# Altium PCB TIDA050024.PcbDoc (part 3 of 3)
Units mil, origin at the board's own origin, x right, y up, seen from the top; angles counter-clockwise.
Board outline 5500.19 x 3301.39 mil, 4 copper layers (Top Layer, Signal Layer 1, Signal Layer 2, Bottom Layer), stack 46.8 mil thick; 153 components, 88 nets, 368 pads, 374 vias.
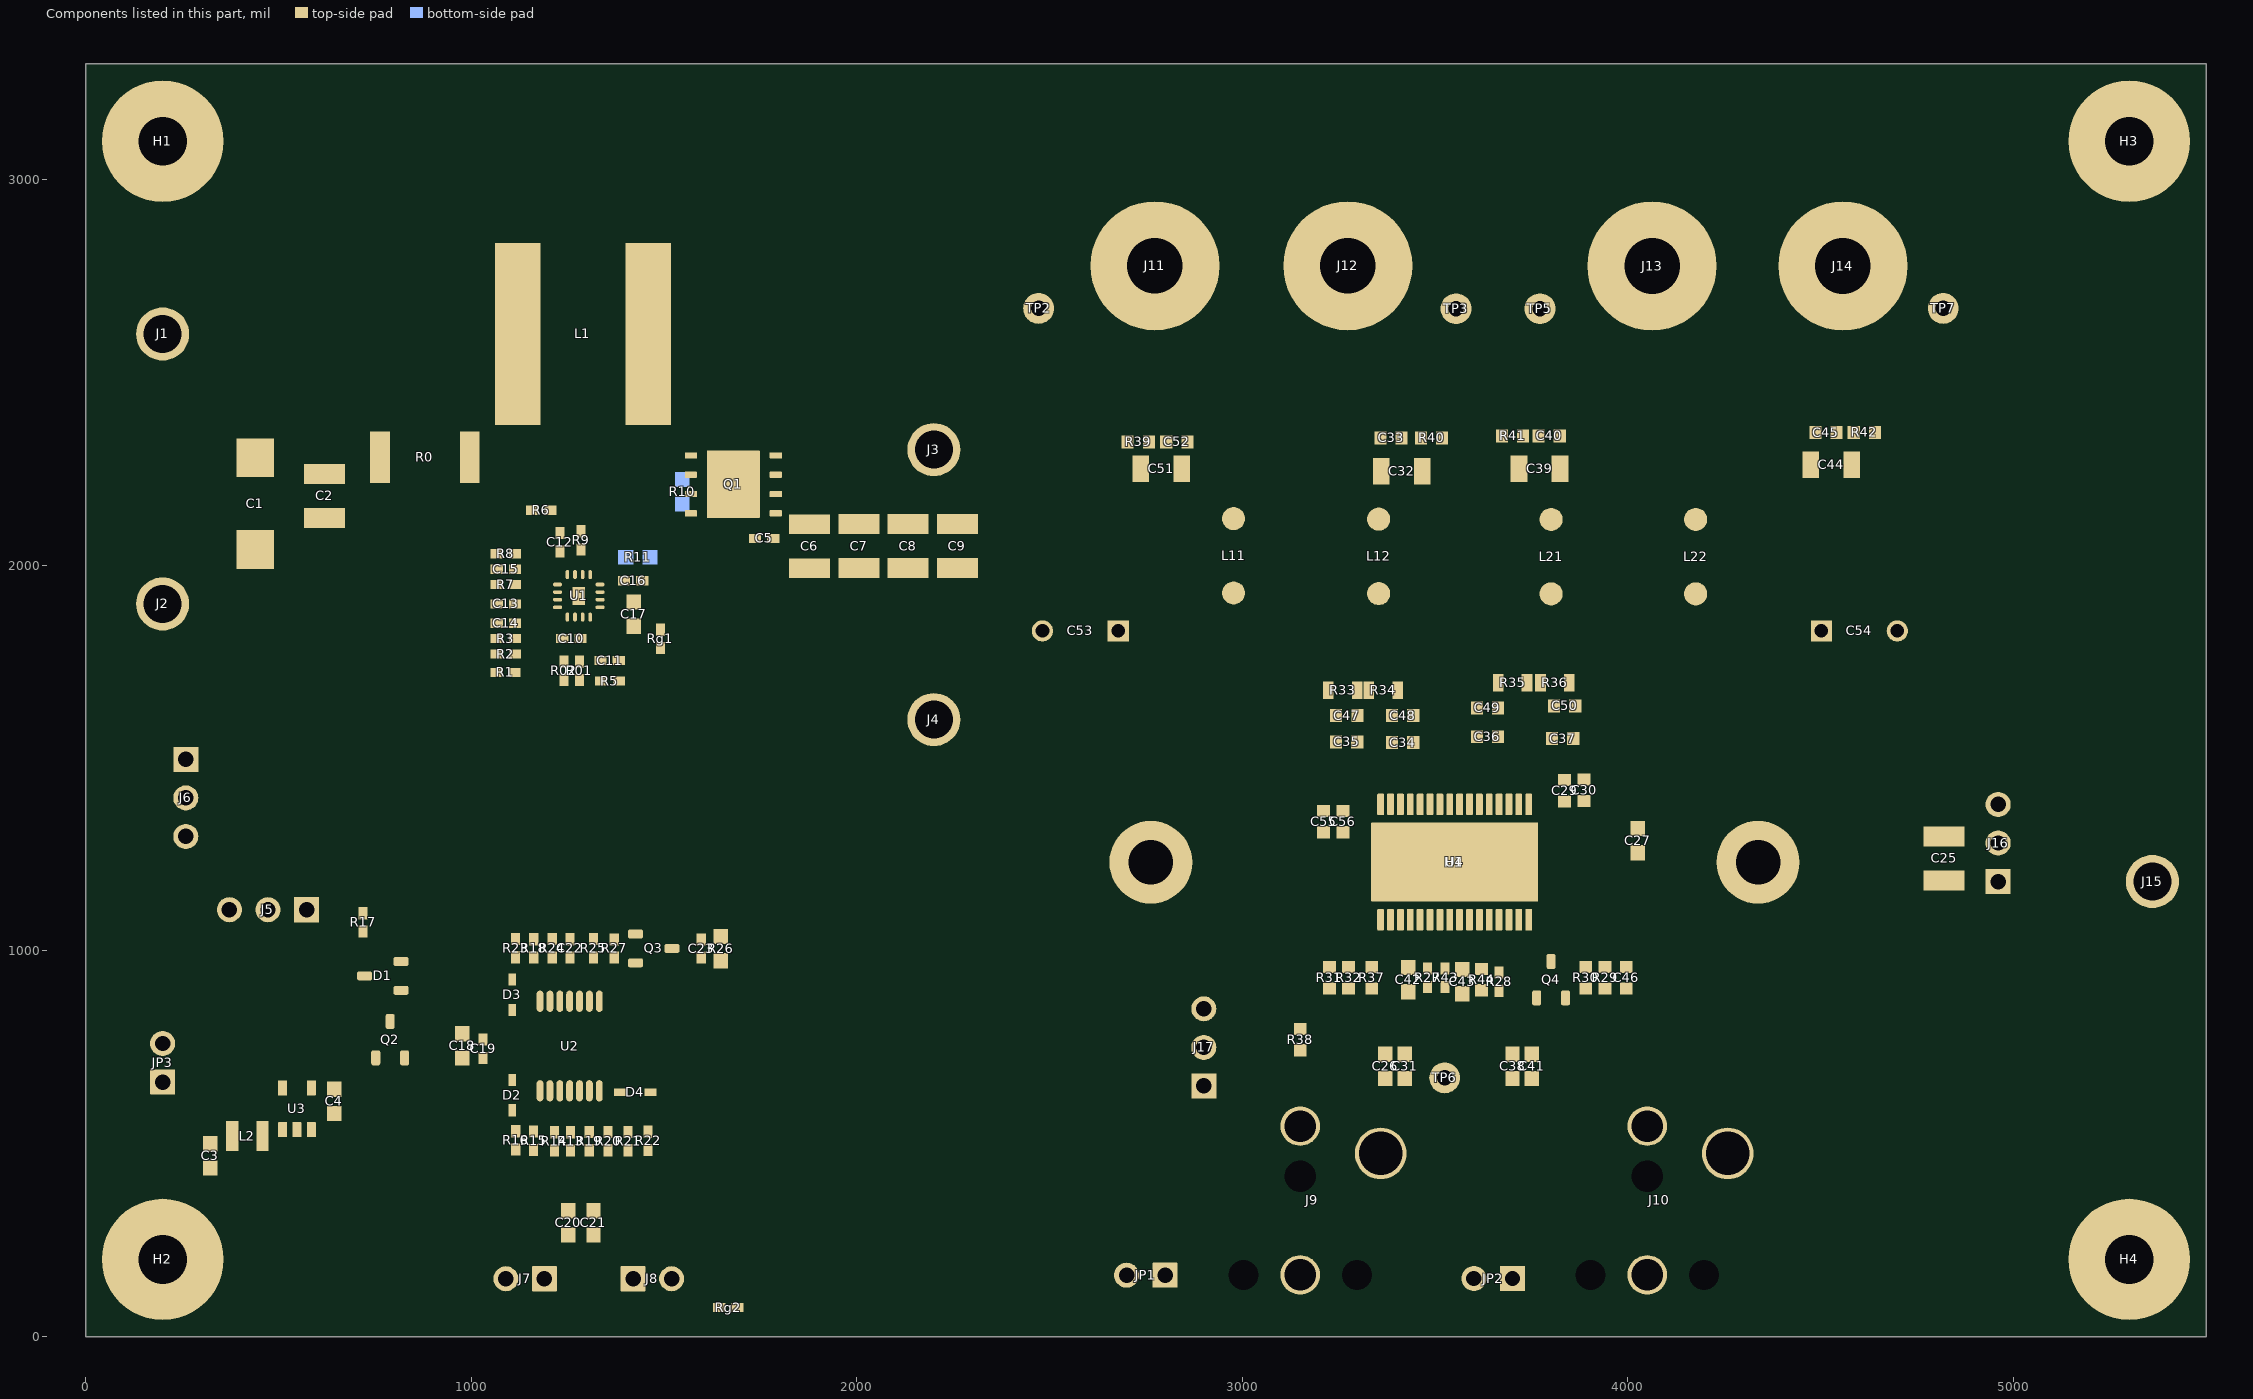
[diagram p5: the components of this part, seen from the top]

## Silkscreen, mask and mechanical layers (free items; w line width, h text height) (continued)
M11 Gerber Information:
  lines w10: -292,-930.17 6308,-930.17 ; -292,-726.83 6310,-726.83 ; -292,-523.5 -292,-1133.5 3713,-1133.5 6310,-1133.5 6310,-523.5 -291.5,-523.5 -291.5,-1133.5 1284,-1133.5 ; 2173,-1133.5 2173,-523.5 ; 3440,-726.83 3440,-523.5 ; 4280,-726.83 4280,-523.5 ; 4902,-1140 4902,-937.17
  text "ALL ARTWORK VIEWED FROM TOP SIDE" at -228.5,-655.67 h30
  text "BOARD #:" at 2248,-655.67 h30
  text ".PRJ_Number" at 2793.5,-655.67 h30
  text "REV:" at 3638,-655.67 h30
  text ".PCB_Rev" at 3929.5,-655.67 h30
  text "SVN REV:" at 4476,-655.67 h30
  text ".VersionControl_RevNumber" at 4982,-655.67 h30
  text "LAYER NAME =" at -228.5,-858.49 h30
  text "TID #:" at 2248,-859 h30
  text ".TID" at 2793.5,-859 h30
  text "PLOT NAME =" at -228.5,-1064.34 h30
  text ".plot_File_Name" at 577,-1064.34 h30
  text "GENERATED    :" at 2250,-1064.34 h30
  text ".Print_Date" at 3119.5,-1064.34 h30
  text ".Print_Time" at 3848.5,-1064.34 h30
  text "TEXAS INSTRUMENTS" at 5113,-1064.34 h30
M12 Stackup:
  drawing of 269 lines, arcs and shapes, not listed
  text "Layer" at 9767.84,7890 h30
  text "Name" at 9982.8,7890 h30
  text "Material" at 10462.67,7890 h30
  text "Thickness" at 10902.55,7890 h30
  text "Constant" at 11237.47,7890 h30
  text "Board Layer Stack" at 11532.4,7890 h30
  text "1" at 9767.84,7830 h30
  text "Top Overlay" at 9982.8,7830 h30
  text "2" at 9767.84,7770 h30
  text "Top Solder" at 9982.8,7770 h30
  text "Solder Resist" at 10462.67,7770 h30
  text "0.40mil" at 10902.55,7770 h30
  text "3.5" at 11237.47,7770 h30
  text "3" at 9767.84,7710 h30
  text "Top Layer" at 9982.8,7710 h30
  text "Copper" at 10462.67,7710 h30
  text "2.80mil" at 10902.55,7710 h30
  text "4" at 9767.84,7650 h30
  text "Dielectric1" at 9982.8,7650 h30
  text "FR-4" at 10462.67,7650 h30
  text "12.80mil" at 10902.55,7650 h30
  text "4.2" at 11237.47,7650 h30
  text "5" at 9767.84,7590 h30
  text "Signal Layer 1" at 9982.8,7590 h30
  text "Copper" at 10462.67,7590 h30
  text "1.40mil" at 10902.55,7590 h30
  text "6" at 9767.84,7530 h30
  text "Dielectric 3" at 9982.8,7530 h30
  text "12.80mil" at 10902.55,7530 h30
  text "4.2" at 11237.47,7530 h30
  text "7" at 9767.84,7470 h30
  text "Signal Layer 2" at 9982.8,7470 h30
  text "Copper" at 10462.67,7470 h30
  text "1.40mil" at 10902.55,7470 h30
  text "8" at 9767.84,7410 h30
  text "Dielectric 2" at 9982.8,7410 h30
  text "12.80mil" at 10902.55,7410 h30
  text "4.2" at 11237.47,7410 h30
  text "9" at 9767.84,7350 h30
  text "Bottom Layer" at 9982.8,7350 h30
  text "Copper" at 10462.67,7350 h30
  text "2.80mil" at 10902.55,7350 h30
  text "10" at 9767.84,7290 h30
  text "Bottom Solder" at 9982.8,7290 h30
  text "Solder Resist" at 10462.67,7290 h30
  text "0.40mil" at 10902.55,7290 h30
  text "3.5" at 11237.47,7290 h30
  text ".Layer_Name" at 577,-858.49 h30
M13 Component Bodies Top:
  text ".Layer_Name" at 577,-858.49 h30
M14 Component Bodies Bottom:
  text ".Layer_Name" at 577,-858.49 h30
M15 Courtyards Top:
  text ".Layer_Name" at 577,-858.49 h30
M16 Courtyards Bottom:
  text ".Layer_Name" at 577,-858.49 h30
Drill Drawing:
  text ".Layer_Name" at 577,-858.49 h30

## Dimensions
0,0 to 3401.28,-18 on M2 Board Dimensions
0,0 to -47.76,2398.56 on M2 Board Dimensions
0,-400 to 1000,-400 on M2 Board Dimensions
